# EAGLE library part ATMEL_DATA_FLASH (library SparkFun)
4Mbit EEPROM DataFlash Footprint needs touching up. Spark Fun Electronics SKU : IC-DataFlash
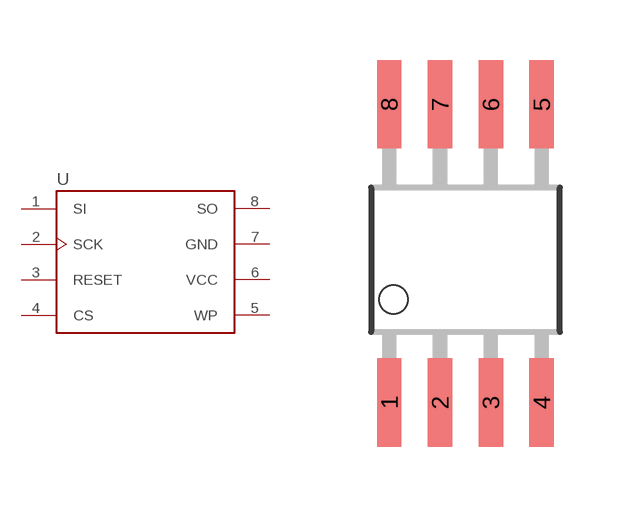
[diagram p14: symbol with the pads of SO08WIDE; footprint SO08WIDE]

Designator prefix -

## ATMEL_DATA_FLASH  [SO08WIDE]
1  SI  in
2  SCK  in
3  RESET
4  CS  in
5  WP
6  VCC  pwr
7  GND  pwr
8  SO  out

## Footprint SO08WIDE (pad centres in mm)
smd 0.61 x 2.21: 1 -1.905,-3.569; 2 -0.635,-3.569; 3 0.635,-3.569; 4 1.905,-3.569; 5 1.905,3.886; 6 0.635,3.886; 7 -0.635,3.886; 8 -1.905,3.886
